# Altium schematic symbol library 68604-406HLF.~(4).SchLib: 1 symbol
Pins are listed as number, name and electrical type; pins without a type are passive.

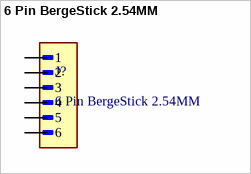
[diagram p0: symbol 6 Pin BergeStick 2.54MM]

## 6 Pin BergeStick 2.54MM
designator J?
6 Pin 6Pos THT BergeStick 2.54MM Amphenol 68604-406HLF 3A; MF: AMPHENOL ICC / FCI
footprint 6 Pin BergeStick 2.54MM (6 Pin 6Pos THT BergeStick 2.54MM Amphenol 68604-406HLF 3A AMPHENOL_68604-406HLF)
pins: 1, 2, 3, 4, 5, 6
